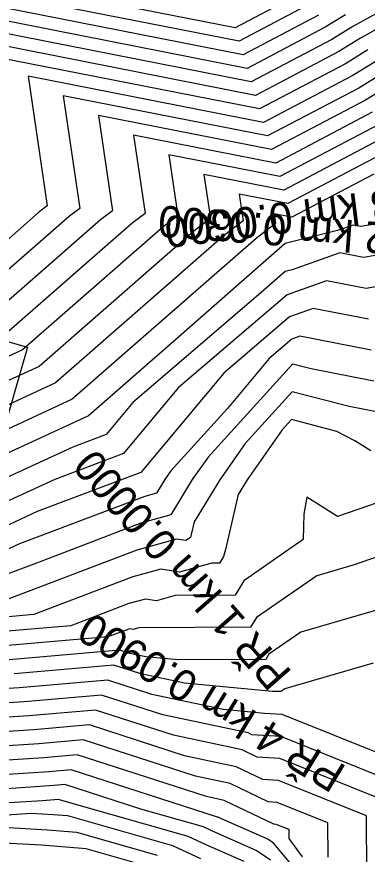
# Model space of a CAD drawing. Extents: x -549394 to -546608, y -1037055 to -1033629.
# Drawn here: x -547310 to -547208.6, y -1036274.8 to -1036032.2 of the extents above; entities that cross this region are included whole.
import ezdxf

# ---------------------------------------------------------------- set-up
doc = ezdxf.new("R2010")
doc.units = 0
for name, color, linetype in [('hlavni_vrst', 7, 'Continuous'), ('norm_vrst', 7, 'Continuous'), ('x_popis_oblouky_C412', 7, 'Continuous'), ('x_popis_pricne_rezy_C412', 7, 'Continuous')]:
    doc.layers.add(name, color=color, linetype=linetype)

msp = doc.modelspace()

# ---------------------------------------------------------------- linework, layer by layer
at = {"layer": 'hlavni_vrst'}
for p, q in [((-547161.94, -1036006.74), (-547212.7, -1036035.07)), ((-547242.13, -1036051.11), (-547337.27, -1036032.37)), ((-547212.7, -1036035.07), (-547218.78, -1036038.81)), ((-547218.78, -1036038.81), (-547242.13, -1036051.11)), ((-547202.05, -1036052.05), (-547209.1, -1036056.41)), ((-547209.1, -1036056.41), (-547236.25, -1036070.69)), ((-547286.38, -1036060.82), (-547282.33, -1036088.47)), ((-547236.25, -1036070.69), (-547286.38, -1036060.82)), ((-547206.64, -1036077.79), (-547230.36, -1036090.28)), ((-547282.33, -1036088.47), (-547285.75, -1036091.08)), ((-547285.75, -1036091.08), (-547317.86, -1036119.19)), ((-547235.49, -1036089.27), (-547235.08, -1036092.1)), ((-547230.36, -1036090.28), (-547235.49, -1036089.27)), ((-547235.08, -1036092.1), (-547240.75, -1036096.43)), ((-547240.75, -1036096.43), (-547293.98, -1036143.02)), ((-547228.09, -1036124.77), (-547230.43, -1036125.6)), ((-547207.41, -1036128.8), (-547228.09, -1036124.77)), ((-547230.43, -1036125.6), (-547236.94, -1036131.17)), ((-547236.94, -1036131.17), (-547248.99, -1036145.66)), ((-547293.98, -1036143.02), (-547330.8, -1036160)), ((-547248.99, -1036145.66), (-547265.39, -1036163.7)), ((-547265.39, -1036163.7), (-547267.17, -1036166.24)), ((-547267.17, -1036166.24), (-547269.59, -1036170.23)), ((-547272.99, -1036171.18), (-547284.47, -1036175.56)), ((-547269.59, -1036170.23), (-547272.99, -1036171.18)), ((-547284.47, -1036175.56), (-547309.19, -1036184.88)), ((-547309.19, -1036184.88), (-547321.53, -1036190.57)), ((-547198.53, -1036186.1), (-547212.4, -1036190.97)), ((-547212.4, -1036190.97), (-547223.21, -1036194.11)), ((-547223.21, -1036194.11), (-547240.67, -1036206.21)), ((-547240.67, -1036206.21), (-547242.36, -1036209.04)), ((-547278.66, -1036209.93), (-547283.64, -1036211.83)), ((-547277.26, -1036209.54), (-547278.66, -1036209.93)), ((-547276.32, -1036209.7), (-547277.26, -1036209.54)), ((-547274.7, -1036209.24), (-547276.32, -1036209.7)), ((-547242.36, -1036209.04), (-547274.7, -1036209.24)), ((-547283.64, -1036211.83), (-547313.63, -1036214.46)), ((-547287.23, -1036233), (-547306.47, -1036234.68)), ((-547264.6, -1036240.32), (-547287.23, -1036233)), ((-547306.47, -1036234.68), (-547344.82, -1036237.24)), ((-547244.76, -1036244.54), (-547264.6, -1036240.32)), ((-547240.4, -1036246.64), (-547244.76, -1036244.54)), ((-547233.92, -1036247.04), (-547240.4, -1036246.64)), ((-547197.57, -1036261.66), (-547233.92, -1036247.04)), ((-547299.32, -1036254.9), (-547360.96, -1036259.03)), ((-547296.06, -1036254.62), (-547299.32, -1036254.9)), ((-547274.12, -1036261.72), (-547296.06, -1036254.62)), ((-547256.01, -1036266.88), (-547274.12, -1036261.72)), ((-547253.37, -1036268.09), (-547256.01, -1036266.88)), ((-547240.76, -1036273.66), (-547253.37, -1036268.09)), ((-547236.58, -1036276.5), (-547240.76, -1036273.66))]:
    msp.add_line(p, q, dxfattribs=at)
at = {"layer": 'norm_vrst'}
for p, q in [((-547165.09, -1036013.08), (-547210.57, -1036038.46)), ((-547246.84, -1036035.44), (-547355.52, -1036014.04)), ((-547245.66, -1036039.35), (-547358.4, -1036017.15)), ((-547244.48, -1036043.27), (-547357.62, -1036020.99)), ((-547226.52, -1036024.74), (-547246.84, -1036035.44)), ((-547243.31, -1036047.19), (-547347.44, -1036026.68)), ((-547224.58, -1036028.26), (-547245.66, -1036039.35)), ((-547222.65, -1036031.78), (-547244.48, -1036043.27)), ((-547214.84, -1036031.67), (-547220.71, -1036035.3)), ((-547220.71, -1036035.3), (-547243.31, -1036047.19)), ((-547240.95, -1036055.02), (-547327.09, -1036038.06)), ((-547210.57, -1036038.46), (-547216.84, -1036042.33)), ((-547216.84, -1036042.33), (-547240.95, -1036055.02)), ((-547208.44, -1036041.86), (-547214.91, -1036045.85)), ((-547239.78, -1036058.94), (-547316.91, -1036043.75)), ((-547206.31, -1036045.26), (-547212.97, -1036049.37)), ((-547214.91, -1036045.85), (-547239.78, -1036058.94)), ((-547306.73, -1036049.44), (-547301.23, -1036087.02)), ((-547238.6, -1036062.86), (-547306.73, -1036049.44)), ((-547212.97, -1036049.37), (-547238.6, -1036062.86)), ((-547204.18, -1036048.65), (-547211.04, -1036052.89)), ((-547211.04, -1036052.89), (-547237.42, -1036066.77)), ((-547296.56, -1036055.13), (-547291.78, -1036087.75)), ((-547237.42, -1036066.77), (-547296.56, -1036055.13)), ((-547207.17, -1036059.92), (-547235.07, -1036074.61)), ((-547205.23, -1036063.44), (-547233.89, -1036078.53)), ((-547276.2, -1036066.51), (-547272.88, -1036089.2)), ((-547235.07, -1036074.61), (-547276.2, -1036066.51)), ((-547203.3, -1036066.96), (-547232.71, -1036082.44)), ((-547201.37, -1036070.48), (-547231.54, -1036086.36)), ((-547266.02, -1036072.2), (-547263.43, -1036089.92)), ((-547233.89, -1036078.53), (-547266.02, -1036072.2)), ((-547255.85, -1036077.89), (-547253.98, -1036090.65)), ((-547232.71, -1036082.44), (-547255.85, -1036077.89)), ((-547245.67, -1036083.58), (-547244.53, -1036091.37)), ((-547231.54, -1036086.36), (-547245.67, -1036083.58)), ((-547303.76, -1036088.94), (-547327.42, -1036109.66)), ((-547301.23, -1036087.02), (-547303.76, -1036088.94)), ((-547291.78, -1036087.75), (-547294.76, -1036090.01)), ((-547294.76, -1036090.01), (-547322.64, -1036114.42)), ((-547272.88, -1036089.2), (-547276.75, -1036092.15)), ((-547263.43, -1036089.92), (-547267.75, -1036093.22)), ((-547253.98, -1036090.65), (-547258.75, -1036094.29)), ((-547244.53, -1036091.37), (-547249.75, -1036095.36)), ((-547188.34, -1036089.23), (-547210.45, -1036093.02)), ((-547276.75, -1036092.15), (-547313.09, -1036123.96)), ((-547267.75, -1036093.22), (-547308.31, -1036128.72)), ((-547212.67, -1036092.59), (-547217.14, -1036094.19)), ((-547210.45, -1036093.02), (-547212.67, -1036092.59)), ((-547157.48, -1036093), (-547209.69, -1036101.97)), ((-547258.75, -1036094.29), (-547303.54, -1036133.49)), ((-547249.75, -1036095.36), (-547298.76, -1036138.26)), ((-547217.14, -1036094.19), (-547232.29, -1036097.92)), ((-547232.29, -1036097.92), (-547263.21, -1036125.03)), ((-547216.52, -1036100.64), (-547230.31, -1036105.55)), ((-547209.69, -1036101.97), (-547216.52, -1036100.64)), ((-547165.77, -1036103.5), (-547208.93, -1036110.91)), ((-547230.31, -1036105.55), (-547232.29, -1036106.04)), ((-547232.29, -1036106.04), (-547240.02, -1036112.82)), ((-547220.38, -1036108.68), (-547231.74, -1036112.73)), ((-547208.93, -1036110.91), (-547220.38, -1036108.68)), ((-547240.02, -1036112.82), (-547276.46, -1036143.97)), ((-547231.74, -1036112.73), (-547263.28, -1036139.71)), ((-547224.23, -1036116.72), (-547231.08, -1036119.17)), ((-547208.17, -1036119.85), (-547224.23, -1036116.72)), ((-547231.08, -1036119.17), (-547250.11, -1036135.44)), ((-547263.21, -1036125.03), (-547289.21, -1036147.79)), ((-547308.31, -1036128.72), (-547336.36, -1036141.66)), ((-547303.54, -1036133.49), (-547334.51, -1036147.77)), ((-547230.16, -1036132.81), (-547254.65, -1036159.77)), ((-547224.8, -1036134.2), (-547230.16, -1036132.81)), ((-547206.65, -1036137.74), (-547224.8, -1036134.2)), ((-547250.11, -1036135.44), (-547274.08, -1036164.24)), ((-547298.76, -1036138.26), (-547332.65, -1036153.88)), ((-547263.28, -1036139.71), (-547279.13, -1036158.75)), ((-547230.31, -1036140.87), (-547243.91, -1036155.84)), ((-547213.78, -1036145.14), (-547230.31, -1036140.87)), ((-547276.46, -1036143.97), (-547284.17, -1036153.25)), ((-547205.89, -1036146.68), (-547213.78, -1036145.14)), ((-547289.21, -1036147.79), (-547328.95, -1036166.11)), ((-547230.45, -1036148.92), (-547233.17, -1036151.91)), ((-547217.37, -1036152.31), (-547230.45, -1036148.92)), ((-547233.17, -1036151.91), (-547243.31, -1036166.35)), ((-547284.17, -1036153.25), (-547293.83, -1036156.89)), ((-547212.13, -1036155.02), (-547217.37, -1036152.31)), ((-547243.91, -1036155.84), (-547251.27, -1036166.31)), ((-547207.53, -1036157.95), (-547212.13, -1036155.02)), ((-547293.83, -1036156.89), (-547327.09, -1036172.23)), ((-547279.13, -1036158.75), (-547298.95, -1036166.22)), ((-547254.65, -1036159.77), (-547259.22, -1036166.28)), ((-547298.95, -1036166.22), (-547325.24, -1036178.34)), ((-547274.08, -1036164.24), (-547304.07, -1036175.55)), ((-547259.22, -1036166.28), (-547265.41, -1036176.49)), ((-547251.27, -1036166.31), (-547258.66, -1036178.51)), ((-547243.31, -1036166.35), (-547245.91, -1036170.63)), ((-547245.91, -1036170.63), (-547249.62, -1036186.56)), ((-547226.03, -1036171.38), (-547226.93, -1036176.31)), ((-547217.22, -1036177.01), (-547226.03, -1036171.38)), ((-547201.57, -1036171.51), (-547217.22, -1036177.01)), ((-547304.07, -1036175.55), (-547323.39, -1036184.45)), ((-547265.41, -1036176.49), (-547274.12, -1036178.93)), ((-547258.66, -1036178.51), (-547259.51, -1036182.19)), ((-547226.93, -1036176.31), (-547227.11, -1036183.63)), ((-547274.12, -1036178.93), (-547303.56, -1036190.15)), ((-547263.82, -1036183.49), (-547275.26, -1036186.68)), ((-547261.11, -1036183.93), (-547263.82, -1036183.49)), ((-547259.74, -1036183.01), (-547261.11, -1036183.93)), ((-547259.51, -1036182.19), (-547259.74, -1036183.01)), ((-547227.11, -1036183.63), (-547244.34, -1036195.57)), ((-547275.26, -1036186.68), (-547315.79, -1036202.13)), ((-547249.62, -1036186.56), (-547250.16, -1036188.56)), ((-547303.56, -1036190.15), (-547314.31, -1036194.21)), ((-547253.55, -1036190.46), (-547262.87, -1036193.07)), ((-547251.29, -1036190.44), (-547253.55, -1036190.46)), ((-547250.16, -1036188.56), (-547251.29, -1036190.44)), ((-547268.3, -1036192.17), (-547276.39, -1036194.43)), ((-547262.87, -1036193.07), (-547268.3, -1036192.17)), ((-547276.39, -1036194.43), (-547305.07, -1036205.37)), ((-547244.34, -1036195.57), (-547246.83, -1036199.74)), ((-547264.12, -1036199.85), (-547269.6, -1036201.38)), ((-547246.83, -1036199.74), (-547264.12, -1036199.85)), ((-547277.53, -1036202.18), (-547294.36, -1036208.6)), ((-547272.78, -1036200.86), (-547277.53, -1036202.18)), ((-547269.6, -1036201.38), (-547272.78, -1036200.86)), ((-547305.07, -1036205.37), (-547316.49, -1036206.37)), ((-547202.22, -1036203.05), (-547227.82, -1036210.48)), ((-547294.36, -1036208.6), (-547315.06, -1036210.41)), ((-547227.82, -1036210.48), (-547237.01, -1036216.85)), ((-547280.16, -1036215.7), (-547312.2, -1036218.5)), ((-547277.3, -1036216.63), (-547280.16, -1036215.7)), ((-547272.64, -1036217.62), (-547277.3, -1036216.63)), ((-547237.01, -1036216.85), (-547237.9, -1036218.34)), ((-547263.28, -1036218.5), (-547272.64, -1036217.62)), ((-547237.9, -1036218.34), (-547263.28, -1036218.5)), ((-547206.86, -1036219.43), (-547232.43, -1036226.86)), ((-547281.93, -1036220.02), (-547310.77, -1036222.54)), ((-547274.12, -1036222.55), (-547281.93, -1036220.02)), ((-547283.7, -1036224.35), (-547309.34, -1036226.59)), ((-547270.95, -1036228.47), (-547283.7, -1036224.35)), ((-547261.43, -1036225.25), (-547274.12, -1036222.55)), ((-547309.34, -1036226.59), (-547338.36, -1036228.53)), ((-547235.95, -1036227.65), (-547261.43, -1036225.25)), ((-547232.43, -1036226.86), (-547233.34, -1036227.49)), ((-547285.46, -1036228.67), (-547307.9, -1036230.63)), ((-547267.77, -1036234.4), (-547285.46, -1036228.67)), ((-547250.22, -1036232.88), (-547270.95, -1036228.47)), ((-547233.43, -1036227.64), (-547235.95, -1036227.65)), ((-547233.34, -1036227.49), (-547233.43, -1036227.64)), ((-547307.9, -1036230.63), (-547341.59, -1036232.89)), ((-547243.03, -1036239.66), (-547267.77, -1036234.4)), ((-547238.32, -1036234.01), (-547250.22, -1036232.88)), ((-547233.24, -1036234.32), (-547238.32, -1036234.01)), ((-547199.85, -1036247.75), (-547233.24, -1036234.32)), ((-547305.04, -1036238.72), (-547348.05, -1036241.6)), ((-547288.99, -1036237.32), (-547305.04, -1036238.72)), ((-547261.42, -1036246.24), (-547288.99, -1036237.32)), ((-547290.76, -1036241.65), (-547303.61, -1036242.77)), ((-547258.25, -1036252.17), (-547290.76, -1036241.65)), ((-547242, -1036240.16), (-547243.03, -1036239.66)), ((-547233.58, -1036240.68), (-547242, -1036240.16)), ((-547186.37, -1036259.67), (-547233.58, -1036240.68)), ((-547303.61, -1036242.77), (-547351.28, -1036245.96)), ((-547292.53, -1036245.97), (-547302.18, -1036246.81)), ((-547255.07, -1036258.09), (-547292.53, -1036245.97)), ((-547246.5, -1036249.42), (-547261.42, -1036246.24)), ((-547302.18, -1036246.81), (-547354.5, -1036250.31)), ((-547300.75, -1036250.86), (-547357.73, -1036254.67)), ((-547294.29, -1036250.29), (-547300.75, -1036250.86)), ((-547251.9, -1036264.01), (-547294.29, -1036250.29)), ((-547238.81, -1036253.12), (-547246.5, -1036249.42)), ((-547248.23, -1036254.3), (-547258.25, -1036252.17)), ((-547234.26, -1036253.4), (-547238.81, -1036253.12)), ((-547208.76, -1036263.66), (-547234.26, -1036253.4)), ((-547237.21, -1036259.6), (-547248.23, -1036254.3)), ((-547249.97, -1036259.18), (-547255.07, -1036258.09)), ((-547302.54, -1036259.26), (-547362.75, -1036263.13)), ((-547297.89, -1036258.95), (-547302.54, -1036259.26)), ((-547297.82, -1036258.94), (-547297.89, -1036258.95)), ((-547297.39, -1036259.08), (-547297.82, -1036258.94)), ((-547260.43, -1036269.62), (-547297.39, -1036259.08)), ((-547235.62, -1036266.08), (-547249.97, -1036259.18)), ((-547234.6, -1036259.76), (-547237.21, -1036259.6)), ((-547219.95, -1036265.66), (-547234.6, -1036259.76)), ((-547305.81, -1036263.01), (-547360.45, -1036266.52)), ((-547299.5, -1036263.35), (-547305.81, -1036263.01)), ((-547295.25, -1036263.69), (-547299.5, -1036263.35)), ((-547264.85, -1036272.35), (-547295.25, -1036263.69)), ((-547251.7, -1036264.05), (-547251.9, -1036264.01)), ((-547250.8, -1036264.49), (-547251.7, -1036264.05)), ((-547237.3, -1036270.44), (-547250.8, -1036264.49)), ((-547219.92, -1036275.58), (-547219.95, -1036265.66)), ((-547208.71, -1036280.94), (-547208.76, -1036263.66)), ((-547301.16, -1036267.76), (-547313.91, -1036267.06)), ((-547292.58, -1036268.45), (-547301.16, -1036267.76)), ((-547234.94, -1036266.12), (-547235.62, -1036266.08)), ((-547231.14, -1036267.65), (-547234.94, -1036266.12)), ((-547231.14, -1036270.23), (-547231.14, -1036267.65)), ((-547269.27, -1036275.09), (-547292.58, -1036268.45)), ((-547255.04, -1036272.1), (-547260.43, -1036269.62)), ((-547235.66, -1036271.56), (-547237.3, -1036270.44)), ((-547227.33, -1036275.5), (-547231.14, -1036270.23)), ((-547302.83, -1036272.17), (-547322.02, -1036271.12)), ((-547289.92, -1036273.21), (-547302.83, -1036272.17)), ((-547273.69, -1036277.83), (-547289.92, -1036273.21)), ((-547256.71, -1036276.1), (-547264.85, -1036272.35)), ((-547244.21, -1036276.88), (-547255.04, -1036272.1)), ((-547234.51, -1036272.91), (-547235.66, -1036271.56)), ((-547199.74, -1036314.48), (-547234.51, -1036272.91))]:
    msp.add_line(p, q, dxfattribs=at)
at = {"layer": 'x_popis_oblouky_C412'}
msp.add_lwpolyline([(-547306.9, -1036127.96), (-547315.34, -1036156.75), (-547321.1, -1036155.06), (-547312.66, -1036126.27)], close=True, dxfattribs=at)

# ---------------------------------------------------------------- texts
at = {"layer": 'x_popis_pricne_rezy_C412'}
for s, rotation, p in [('PŘ 3 km 0.0600', 187.1428, (-547181.41, -1036079.46)), ('PŘ 2 km 0.0300', 175.6203, (-547182.02, -1036093.48)), ('PŘ 1 km 0.0000', 131.2978, (-547230.05, -1036222.11)), ('PŘ 4 km 0.0900', 148.7126, (-547214.2, -1036249.54)), ('PŘ 5 km 0.1051', 117.4888, (-547308.28, -1036342.72))]:
    msp.add_text(s, height=9.0627, rotation=rotation, dxfattribs=at).set_placement(p)

doc.saveas('drawing.dxf')
